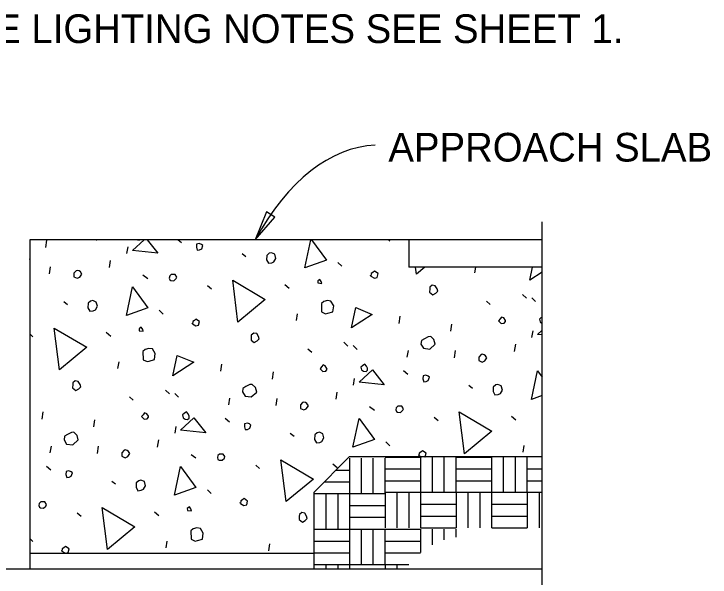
# Model space of a CAD drawing. Extents: x -1660015.2 to -1659984.9, y 2580594.2 to 2580616.7.
# Drawn here: x -1659989.055 to -1659985.382, y 2580602.277 to 2580605.246 of the extents above; entities that cross this region are included whole.
import ezdxf

# ---------------------------------------------------------------- set-up
doc = ezdxf.new("R2010")
doc.units = 0
for name, color, linetype in [('Default', 7, 'Continuous'), ('Miscellaneous', 7, 'Continuous'), ('Miscellaneous3', 7, 'Continuous'), ('PlotBorder_dp', 7, 'Continuous'), ('SheetLines_dp', 7, 'Continuous')]:
    doc.layers.add(name, color=color, linetype=linetype)

msp = doc.modelspace()

# ---------------------------------------------------------------- linework, layer by layer
at = {"layer": 'Default'}
msp.add_line((-1659986.2685, 2580602.3187), (-1659989.3273, 2580602.3187), dxfattribs=at)
at = {"layer": 'Miscellaneous'}
for p, q in [((-1659988.8871, 2580604.0154), (-1659988.8816, 2580604.0531)), ((-1659988.1893, 2580604.056), (-1659988.1719, 2580604.0414)), ((-1659987.0793, 2580604.056), (-1659987.0714, 2580604.049)), ((-1659986.2685, 2580604.056), (-1659986.972, 2580604.056)), ((-1659988.459, 2580603.9826), (-1659988.4529, 2580604.0178)), ((-1659987.8507, 2580603.9825), (-1659987.8311, 2580603.967)), ((-1659988.5505, 2580603.9089), (-1659988.5451, 2580603.9465)), ((-1659987.3466, 2580603.9364), (-1659987.3257, 2580603.9161)), ((-1659988.8677, 2580603.8756), (-1659988.8623, 2580603.9133)), ((-1659986.6228, 2580603.8819), (-1659986.618, 2580603.9102)), ((-1659988.3746, 2580603.8706), (-1659988.3488, 2580603.8516)), ((-1659988.0335, 2580603.8145), (-1659988.0132, 2580603.7966)), ((-1659987.626, 2580603.8201), (-1659987.6027, 2580603.8005)), ((-1659986.3723, 2580603.7678), (-1659986.3513, 2580603.7476)), ((-1659986.3235, 2580603.7498), (-1659986.3025, 2580603.7296)), ((-1659988.7925, 2580603.7301), (-1659988.7728, 2580603.7147)), ((-1659986.5621, 2580603.7325), (-1659986.5418, 2580603.7146)), ((-1659988.2884, 2580603.684), (-1659988.2674, 2580603.6638)), ((-1659987.5646, 2580603.6295), (-1659987.5585, 2580603.6648)), ((-1659987.0222, 2580603.6144), (-1659987.0168, 2580603.6521)), ((-1659986.7499, 2580603.5735), (-1659986.7444, 2580603.6112)), ((-1659988.5678, 2580603.5678), (-1659988.5444, 2580603.5481)), ((-1659986.3218, 2580603.5407), (-1659986.3157, 2580603.5759)), ((-1659988.972, 2580603.5592), (-1659988.9549, 2580603.5443)), ((-1659987.3141, 2580603.5155), (-1659987.2931, 2580603.4952)), ((-1659987.2653, 2580603.4975), (-1659987.2443, 2580603.4772)), ((-1659986.4133, 2580603.4669), (-1659986.4079, 2580603.5046)), ((-1659987.5039, 2580603.4801), (-1659987.4836, 2580603.4623)), ((-1659986.9798, 2580603.4368), (-1659986.9737, 2580603.4721)), ((-1659986.7305, 2580603.4337), (-1659986.7251, 2580603.4714)), ((-1659988.5064, 2580603.3772), (-1659988.5003, 2580603.4124)), ((-1659987.964, 2580603.362), (-1659987.9586, 2580603.3997)), ((-1659987.6916, 2580603.3211), (-1659987.6862, 2580603.3588)), ((-1659986.9999, 2580603.3667), (-1659986.9765, 2580603.3471)), ((-1659987.2636, 2580603.2883), (-1659987.2575, 2580603.3236)), ((-1659986.6553, 2580603.2882), (-1659986.6356, 2580603.2728)), ((-1659988.2558, 2580603.2631), (-1659988.2349, 2580603.2429)), ((-1659988.207, 2580603.2451), (-1659988.1861, 2580603.2249)), ((-1659987.3551, 2580603.2146), (-1659987.3497, 2580603.2523)), ((-1659988.4457, 2580603.2278), (-1659988.4254, 2580603.2099)), ((-1659987.9216, 2580603.1845), (-1659987.9155, 2580603.2197)), ((-1659987.6723, 2580603.1814), (-1659987.6669, 2580603.2191)), ((-1659987.1792, 2580603.1763), (-1659987.1534, 2580603.1574)), ((-1659988.9058, 2580603.1097), (-1659988.9003, 2580603.1474)), ((-1659986.4306, 2580603.1258), (-1659986.4073, 2580603.1062)), ((-1659988.6334, 2580603.0688), (-1659988.628, 2580603.1065)), ((-1659987.9416, 2580603.1144), (-1659987.9183, 2580603.0948)), ((-1659986.838, 2580603.1202), (-1659986.8177, 2580603.1024)), ((-1659988.2053, 2580603.036), (-1659988.1993, 2580603.0712)), ((-1659987.5971, 2580603.0359), (-1659987.5774, 2580603.0204)), ((-1659988.2969, 2580602.9623), (-1659988.2914, 2580602.9999)), ((-1659987.093, 2580602.9898), (-1659987.072, 2580602.9695)), ((-1659988.8634, 2580602.9321), (-1659988.8573, 2580602.9674)), ((-1659988.6141, 2580602.929), (-1659988.6087, 2580602.9667)), ((-1659986.3692, 2580602.9352), (-1659986.3631, 2580602.9705)), ((-1659988.121, 2580602.924), (-1659988.0952, 2580602.905)), ((-1659987.2832, 2580602.5297), (-1659987.2832, 2580602.9035)), ((-1659987.2219, 2580602.7172), (-1659987.2219, 2580602.9035)), ((-1659987.1594, 2580602.7172), (-1659987.1594, 2580602.9035)), ((-1659987.0971, 2580602.9101), (-1659986.9083, 2580602.9101)), ((-1659987.0969, 2580602.7172), (-1659987.0969, 2580602.9035)), ((-1659986.9083, 2580602.5364), (-1659986.9083, 2580602.9101)), ((-1659986.8471, 2580602.7239), (-1659986.8471, 2580602.9101)), ((-1659986.7846, 2580602.7239), (-1659986.7846, 2580602.9101)), ((-1659986.7221, 2580602.9101), (-1659986.5333, 2580602.9101)), ((-1659986.7221, 2580602.7239), (-1659986.7221, 2580602.9101)), ((-1659986.5333, 2580602.5364), (-1659986.5333, 2580602.9101)), ((-1659986.4721, 2580602.7239), (-1659986.4721, 2580602.9101)), ((-1659986.4096, 2580602.7239), (-1659986.4096, 2580602.9101)), ((-1659986.3471, 2580602.7239), (-1659986.3471, 2580602.9101)), ((-1659987.7798, 2580602.8679), (-1659987.7595, 2580602.85)), ((-1659987.3724, 2580602.8735), (-1659987.349, 2580602.8539)), ((-1659988.8834, 2580602.862), (-1659988.86, 2580602.8424)), ((-1659987.3564, 2580602.841), (-1659987.2832, 2580602.841)), ((-1659987.0971, 2580602.8476), (-1659986.9083, 2580602.8476)), ((-1659986.7221, 2580602.8476), (-1659986.5333, 2580602.8476)), ((-1659986.3471, 2580602.8477), (-1659986.2685, 2580602.8477)), ((-1659988.5389, 2580602.7835), (-1659988.5192, 2580602.7681)), ((-1659987.4189, 2580602.7785), (-1659987.2832, 2580602.7785)), ((-1659987.0971, 2580602.7851), (-1659986.9083, 2580602.7851)), ((-1659986.7221, 2580602.7851), (-1659986.5333, 2580602.7851)), ((-1659986.3471, 2580602.7852), (-1659986.2685, 2580602.7852)), ((-1659988.0348, 2580602.7374), (-1659988.0138, 2580602.7172)), ((-1659987.0971, 2580602.7239), (-1659986.7221, 2580602.7239)), ((-1659987.0971, 2580602.7239), (-1659987.0971, 2580602.5364)), ((-1659987.0346, 2580602.7239), (-1659987.0346, 2580602.5364)), ((-1659986.9721, 2580602.7239), (-1659986.9721, 2580602.5364)), ((-1659986.7221, 2580602.7239), (-1659986.3471, 2580602.7239)), ((-1659986.7221, 2580602.7239), (-1659986.7221, 2580602.5364)), ((-1659986.6596, 2580602.7239), (-1659986.6596, 2580602.5364)), ((-1659986.5971, 2580602.7239), (-1659986.5971, 2580602.5364)), ((-1659986.3471, 2580602.7239), (-1659986.2685, 2580602.7239)), ((-1659986.3471, 2580602.7239), (-1659986.3471, 2580602.5364)), ((-1659986.2846, 2580602.7239), (-1659986.2846, 2580602.5364)), ((-1659987.4719, 2580602.7172), (-1659987.0969, 2580602.7172)), ((-1659987.4094, 2580602.7172), (-1659987.4094, 2580602.5297)), ((-1659987.3469, 2580602.7172), (-1659987.3469, 2580602.5297)), ((-1659987.2832, 2580602.6547), (-1659987.0969, 2580602.6547)), ((-1659986.9083, 2580602.6614), (-1659986.7221, 2580602.6614)), ((-1659986.5333, 2580602.6614), (-1659986.3471, 2580602.6614)), ((-1659988.7216, 2580602.6155), (-1659988.7013, 2580602.5977)), ((-1659988.3142, 2580602.6211), (-1659988.2908, 2580602.6015)), ((-1659987.2832, 2580602.5922), (-1659987.0969, 2580602.5922)), ((-1659986.9083, 2580602.5989), (-1659986.7221, 2580602.5989)), ((-1659986.5333, 2580602.5989), (-1659986.3471, 2580602.5989)), ((-1659986.9083, 2580602.5364), (-1659986.7221, 2580602.5364)), ((-1659986.5333, 2580602.5364), (-1659986.3471, 2580602.5364)), ((-1659987.4719, 2580602.5297), (-1659987.2832, 2580602.5297)), ((-1659987.2832, 2580602.3187), (-1659987.2832, 2580602.5298)), ((-1659987.2832, 2580602.5297), (-1659987.0969, 2580602.5297)), ((-1659987.2219, 2580602.3435), (-1659987.2219, 2580602.5297)), ((-1659987.1594, 2580602.3435), (-1659987.1594, 2580602.5297)), ((-1659987.0969, 2580602.5297), (-1659986.9082, 2580602.5297)), ((-1659987.0969, 2580602.3435), (-1659987.0969, 2580602.5297)), ((-1659986.9082, 2580602.4069), (-1659986.9082, 2580602.5298)), ((-1659986.8469, 2580602.447), (-1659986.8469, 2580602.5298)), ((-1659986.7844, 2580602.4735), (-1659986.7844, 2580602.5298)), ((-1659986.7219, 2580602.4875), (-1659986.7219, 2580602.5298)), ((-1659988.972, 2580602.4807), (-1659988.9556, 2580602.4648)), ((-1659988.2528, 2580602.4306), (-1659988.2467, 2580602.4658)), ((-1659987.4719, 2580602.4672), (-1659987.2832, 2580602.4672)), ((-1659987.0969, 2580602.4672), (-1659986.9082, 2580602.4672)), ((-1659987.7104, 2580602.4154), (-1659987.7049, 2580602.4531)), ((-1659987.472, 2580602.402), (-1659988.972, 2580602.402)), ((-1659987.4719, 2580602.4047), (-1659987.2832, 2580602.4047)), ((-1659987.0969, 2580602.4048), (-1659986.9108, 2580602.4048)), ((-1659987.4719, 2580602.3435), (-1659987.0969, 2580602.3435)), ((-1659987.4094, 2580602.3435), (-1659987.4094, 2580602.3187)), ((-1659987.3469, 2580602.3435), (-1659987.3469, 2580602.3187)), ((-1659987.0969, 2580602.3435), (-1659986.9711, 2580602.3435)), ((-1659987.0969, 2580602.3435), (-1659987.0969, 2580602.3187)), ((-1659987.0344, 2580602.3435), (-1659987.0344, 2580602.3187)), ((-1659986.9719, 2580602.3435), (-1659986.9719, 2580602.3425))]:
    msp.add_line(p, q, dxfattribs=at)
for points in [[(-1659988.6212, 2580604.056), (-1659988.6209, 2580604.0556), (-1659988.6176, 2580604.056)], [(-1659988.4295, 2580603.9982), (-1659988.3674, 2580604.056)], [(-1659988.3529, 2580604.056), (-1659988.2965, 2580603.9847), (-1659988.4295, 2580603.9982)], [(-1659988.4041, 2580604.056), (-1659988.3929, 2580604.0546), (-1659988.3914, 2580604.056)], [(-1659987.5202, 2580603.908), (-1659987.4888, 2580604.056)], [(-1659987.486, 2580604.056), (-1659987.4069, 2580603.9487), (-1659987.5202, 2580603.908)], [(-1659988.0926, 2580604.016), (-1659988.0888, 2580604.0015), (-1659988.076, 2580604.0023), (-1659988.0646, 2580604.008), (-1659988.0588, 2580604.0251), (-1659988.0656, 2580604.031), (-1659988.0772, 2580604.0357), (-1659988.0917, 2580604.0318), (-1659988.0926, 2580604.016)], [(-1659987.7214, 2580603.9731), (-1659987.7228, 2580603.9495), (-1659987.7128, 2580603.9314), (-1659987.6953, 2580603.9336), (-1659987.6838, 2580603.9392), (-1659987.6732, 2580603.9576), (-1659987.6791, 2580603.9793), (-1659987.6968, 2580603.9875), (-1659987.7089, 2580603.9843), (-1659987.7214, 2580603.9731)], [(-1659988.972, 2580603.9446), (-1659988.9696, 2580603.9467), (-1659988.972, 2580603.9556)], [(-1659988.7392, 2580603.879), (-1659988.7395, 2580603.8608), (-1659988.7218, 2580603.8526), (-1659988.708, 2580603.8589), (-1659988.6967, 2580603.8749), (-1659988.7048, 2580603.8856), (-1659988.7115, 2580603.8916), (-1659988.7225, 2580603.8938), (-1659988.7273, 2580603.8925), (-1659988.7392, 2580603.879)], [(-1659986.9314, 2580603.8742), (-1659986.9359, 2580603.9102)], [(-1659986.8878, 2580603.9102), (-1659986.9314, 2580603.8742)], [(-1659986.3329, 2580603.8431), (-1659986.3185, 2580603.9102)], [(-1659988.2329, 2580603.8439), (-1659988.2267, 2580603.8403), (-1659988.211, 2580603.8394), (-1659988.1984, 2580603.8505), (-1659988.1955, 2580603.859), (-1659988.2042, 2580603.8722), (-1659988.2249, 2580603.8719), (-1659988.2332, 2580603.8645), (-1659988.2355, 2580603.8535), (-1659988.2329, 2580603.8439)], [(-1659987.172, 2580603.8641), (-1659987.1536, 2580603.8535), (-1659987.1391, 2580603.8574), (-1659987.134, 2580603.8769), (-1659987.153, 2580603.8899), (-1659987.1614, 2580603.8825), (-1659987.1704, 2580603.8775), (-1659987.172, 2580603.8641), (-1659987.1733, 2580603.869)], [(-1659986.2685, 2580603.8845), (-1659986.3329, 2580603.8431)], [(-1659987.8732, 2580603.6219), (-1659987.9011, 2580603.8422), (-1659987.729, 2580603.7408), (-1659987.8732, 2580603.6219)], [(-1659987.4521, 2580603.8279), (-1659987.4309, 2580603.8258), (-1659987.4335, 2580603.8355), (-1659987.4415, 2580603.8463), (-1659987.4523, 2580603.8382), (-1659987.4521, 2580603.8279)], [(-1659988.462, 2580603.6556), (-1659988.4299, 2580603.8066), (-1659988.3486, 2580603.6964), (-1659988.462, 2580603.6556)], [(-1659986.8616, 2580603.7972), (-1659986.8619, 2580603.779), (-1659986.8453, 2580603.7653), (-1659986.8297, 2580603.7747), (-1659986.8195, 2580603.7852), (-1659986.8228, 2580603.7972), (-1659986.8321, 2580603.8128), (-1659986.8485, 2580603.8162), (-1659986.8611, 2580603.8051), (-1659986.8616, 2580603.7972)], [(-1659988.6632, 2580603.7208), (-1659988.6646, 2580603.6971), (-1659988.6546, 2580603.6791), (-1659988.637, 2580603.6812), (-1659988.6256, 2580603.6869), (-1659988.615, 2580603.7052), (-1659988.6208, 2580603.727), (-1659988.6386, 2580603.7352), (-1659988.6506, 2580603.7319), (-1659988.6632, 2580603.7208)], [(-1659987.4333, 2580603.719), (-1659987.432, 2580603.6754), (-1659987.4112, 2580603.6654), (-1659987.3991, 2580603.6687), (-1659987.3726, 2580603.6758), (-1659987.3682, 2580603.708), (-1659987.3826, 2580603.7326), (-1659987.4015, 2580603.7353), (-1659987.4208, 2580603.7302), (-1659987.4333, 2580603.719)], [(-1659987.2747, 2580603.5907), (-1659987.2516, 2580603.6978), (-1659987.1643, 2580603.6617), (-1659987.2747, 2580603.5907)], [(-1659988.1137, 2580603.6118), (-1659988.0954, 2580603.6012), (-1659988.0809, 2580603.6051), (-1659988.0758, 2580603.6245), (-1659988.0948, 2580603.6376), (-1659988.1031, 2580603.6302), (-1659988.1121, 2580603.6251), (-1659988.1137, 2580603.6118), (-1659988.115, 2580603.6166)], [(-1659986.4979, 2580603.628), (-1659986.4837, 2580603.6137), (-1659986.4686, 2580603.6152), (-1659986.4609, 2580603.625), (-1659986.4621, 2580603.6299), (-1659986.4709, 2580603.6431), (-1659986.4825, 2580603.6477), (-1659986.4902, 2580603.6379), (-1659986.4979, 2580603.628)], [(-1659986.2685, 2580603.6479), (-1659986.2744, 2580603.6439), (-1659986.2828, 2580603.6365), (-1659986.2789, 2580603.622)], [(-1659986.2789, 2580603.622), (-1659986.269, 2580603.6143), (-1659986.2685, 2580603.6142)], [(-1659988.8149, 2580603.3695), (-1659988.8429, 2580603.5898), (-1659988.6708, 2580603.4884), (-1659988.8149, 2580603.3695)], [(-1659988.3939, 2580603.5755), (-1659988.3726, 2580603.5735), (-1659988.3752, 2580603.5831), (-1659988.3833, 2580603.5939), (-1659988.3941, 2580603.5858), (-1659988.3939, 2580603.5755)], [(-1659987.8033, 2580603.5448), (-1659987.8036, 2580603.5266), (-1659987.787, 2580603.513), (-1659987.7714, 2580603.5223), (-1659987.7613, 2580603.5328), (-1659987.7645, 2580603.5449), (-1659987.7739, 2580603.5605), (-1659987.7903, 2580603.5639), (-1659987.8029, 2580603.5527), (-1659987.8033, 2580603.5448)], [(-1659986.2923, 2580603.5563), (-1659986.2685, 2580603.5785)], [(-1659986.9076, 2580603.5053), (-1659986.8939, 2580603.4831), (-1659986.8617, 2580603.4788), (-1659986.8324, 2580603.5048), (-1659986.8389, 2580603.5289), (-1659986.8561, 2580603.545), (-1659986.8688, 2580603.5442), (-1659986.8893, 2580603.5335), (-1659986.9049, 2580603.5242), (-1659986.9076, 2580603.5053)], [(-1659986.2685, 2580603.5539), (-1659986.2923, 2580603.5563)], [(-1659988.3751, 2580603.4667), (-1659988.3738, 2580603.4231), (-1659988.353, 2580603.4131), (-1659988.3409, 2580603.4163), (-1659988.3143, 2580603.4234), (-1659988.31, 2580603.4557), (-1659988.3244, 2580603.4803), (-1659988.3432, 2580603.483), (-1659988.3626, 2580603.4778), (-1659988.3751, 2580603.4667)], [(-1659988.2165, 2580603.3384), (-1659988.1934, 2580603.4455), (-1659988.1061, 2580603.4094), (-1659988.2165, 2580603.3384)], [(-1659986.602, 2580603.4371), (-1659986.6023, 2580603.4189), (-1659986.5846, 2580603.4107), (-1659986.5708, 2580603.417), (-1659986.5595, 2580603.433), (-1659986.5676, 2580603.4437), (-1659986.5743, 2580603.4497), (-1659986.5853, 2580603.4519), (-1659986.5901, 2580603.4506), (-1659986.602, 2580603.4371)], [(-1659987.4397, 2580603.3757), (-1659987.4255, 2580603.3614), (-1659987.4103, 2580603.3629), (-1659987.4026, 2580603.3727), (-1659987.4039, 2580603.3775), (-1659987.4126, 2580603.3907), (-1659987.4242, 2580603.3954), (-1659987.432, 2580603.3855), (-1659987.4397, 2580603.3757)], [(-1659987.2207, 2580603.3697), (-1659987.2108, 2580603.362), (-1659987.1975, 2580603.3604), (-1659987.1891, 2580603.3678), (-1659987.1893, 2580603.3781), (-1659987.1949, 2580603.3895), (-1659987.203, 2580603.4003), (-1659987.2162, 2580603.3916), (-1659987.2245, 2580603.3842), (-1659987.2207, 2580603.3697)], [(-1659987.2341, 2580603.304), (-1659987.1636, 2580603.3694), (-1659987.1011, 2580603.2904), (-1659987.2341, 2580603.304)], [(-1659986.3248, 2580603.2137), (-1659986.2927, 2580603.3647), (-1659986.2685, 2580603.3318)], [(-1659988.7451, 2580603.2925), (-1659988.7454, 2580603.2743), (-1659988.7288, 2580603.2606), (-1659988.7132, 2580603.27), (-1659988.7031, 2580603.2805), (-1659988.7063, 2580603.2925), (-1659988.7157, 2580603.3081), (-1659988.7321, 2580603.3115), (-1659988.7446, 2580603.3004), (-1659988.7451, 2580603.2925)], [(-1659986.8972, 2580603.3218), (-1659986.8933, 2580603.3073), (-1659986.8806, 2580603.3081), (-1659986.8692, 2580603.3137), (-1659986.8634, 2580603.3308), (-1659986.8702, 2580603.3368), (-1659986.8818, 2580603.3414), (-1659986.8963, 2580603.3375), (-1659986.8972, 2580603.3218)], [(-1659987.8494, 2580603.253), (-1659987.8357, 2580603.2308), (-1659987.8034, 2580603.2265), (-1659987.7742, 2580603.2524), (-1659987.7806, 2580603.2766), (-1659987.7979, 2580603.2927), (-1659987.8106, 2580603.2918), (-1659987.831, 2580603.2812), (-1659987.8467, 2580603.2718), (-1659987.8494, 2580603.253)], [(-1659986.526, 2580603.2789), (-1659986.5274, 2580603.2552), (-1659986.5174, 2580603.2372), (-1659986.4998, 2580603.2393), (-1659986.4884, 2580603.2449), (-1659986.4778, 2580603.2633), (-1659986.4836, 2580603.2851), (-1659986.5014, 2580603.2932), (-1659986.5134, 2580603.29), (-1659986.526, 2580603.2789)], [(-1659986.2685, 2580603.234), (-1659986.3248, 2580603.2137)], [(-1659987.5438, 2580603.1847), (-1659987.5441, 2580603.1665), (-1659987.5264, 2580603.1584), (-1659987.5125, 2580603.1647), (-1659987.5013, 2580603.1806), (-1659987.5093, 2580603.1914), (-1659987.5161, 2580603.1973), (-1659987.5271, 2580603.1996), (-1659987.5319, 2580603.1983), (-1659987.5438, 2580603.1847)], [(-1659987.0374, 2580603.1496), (-1659987.0313, 2580603.1461), (-1659987.0155, 2580603.1451), (-1659987.003, 2580603.1562), (-1659987.0001, 2580603.1648), (-1659987.0088, 2580603.178), (-1659987.0294, 2580603.1776), (-1659987.0378, 2580603.1702), (-1659987.04, 2580603.1593), (-1659987.0374, 2580603.1496)], [(-1659988.3815, 2580603.1234), (-1659988.3673, 2580603.109), (-1659988.3521, 2580603.1105), (-1659988.3444, 2580603.1203), (-1659988.3457, 2580603.1252), (-1659988.3544, 2580603.1384), (-1659988.366, 2580603.143), (-1659988.3737, 2580603.1332), (-1659988.3815, 2580603.1234)], [(-1659988.1624, 2580603.1173), (-1659988.1526, 2580603.1096), (-1659988.1392, 2580603.108), (-1659988.1309, 2580603.1154), (-1659988.131, 2580603.1257), (-1659988.1367, 2580603.1372), (-1659988.1448, 2580603.148), (-1659988.1579, 2580603.1392), (-1659988.1663, 2580603.1318), (-1659988.1624, 2580603.1173)], [(-1659986.6777, 2580602.9276), (-1659986.7057, 2580603.1479), (-1659986.5336, 2580603.0465), (-1659986.6777, 2580602.9276)], [(-1659988.1759, 2580603.0516), (-1659988.1054, 2580603.1171), (-1659988.0428, 2580603.0381), (-1659988.1759, 2580603.0516)], [(-1659987.839, 2580603.0694), (-1659987.8351, 2580603.0549), (-1659987.8224, 2580603.0557), (-1659987.811, 2580603.0614), (-1659987.8052, 2580603.0785), (-1659987.812, 2580603.0844), (-1659987.8236, 2580603.0891), (-1659987.8381, 2580603.0852), (-1659987.839, 2580603.0694)], [(-1659987.2665, 2580602.9614), (-1659987.2345, 2580603.1123), (-1659987.1532, 2580603.0021), (-1659987.2665, 2580602.9614)], [(-1659988.7911, 2580603.0006), (-1659988.7774, 2580602.9784), (-1659988.7452, 2580602.9741), (-1659988.7159, 2580603.0001), (-1659988.7224, 2580603.0242), (-1659988.7397, 2580603.0403), (-1659988.7524, 2580603.0395), (-1659988.7728, 2580603.0288), (-1659988.7884, 2580603.0195), (-1659988.7911, 2580603.0006)], [(-1659987.4678, 2580603.0265), (-1659987.4692, 2580603.0029), (-1659987.4592, 2580602.9848), (-1659987.4416, 2580602.9869), (-1659987.4302, 2580602.9926), (-1659987.4196, 2580603.011), (-1659987.4254, 2580603.0327), (-1659987.4431, 2580603.0409), (-1659987.4552, 2580603.0377), (-1659987.4678, 2580603.0265)], [(-1659988.4856, 2580602.9324), (-1659988.4859, 2580602.9142), (-1659988.4682, 2580602.906), (-1659988.4543, 2580602.9123), (-1659988.4431, 2580602.9283), (-1659988.4511, 2580602.939), (-1659988.4579, 2580602.945), (-1659988.4688, 2580602.9472), (-1659988.4737, 2580602.9459), (-1659988.4856, 2580602.9324)], [(-1659986.8878, 2580602.9102), (-1659986.8855, 2580602.9108), (-1659986.8803, 2580602.9303), (-1659986.8994, 2580602.9433), (-1659986.9077, 2580602.9359), (-1659986.9167, 2580602.9309), (-1659986.9183, 2580602.9175), (-1659986.9196, 2580602.9224)], [(-1659987.9792, 2580602.8972), (-1659987.9731, 2580602.8937), (-1659987.9573, 2580602.8928), (-1659987.9448, 2580602.9039), (-1659987.9419, 2580602.9124), (-1659987.9506, 2580602.9256), (-1659987.9712, 2580602.9253), (-1659987.9796, 2580602.9179), (-1659987.9818, 2580602.9069), (-1659987.9792, 2580602.8972)], [(-1659986.9183, 2580602.9175), (-1659986.9056, 2580602.9102)], [(-1659987.6195, 2580602.6753), (-1659987.6475, 2580602.8956), (-1659987.4754, 2580602.7941), (-1659987.6195, 2580602.6753)], [(-1659988.7808, 2580602.8171), (-1659988.7769, 2580602.8026), (-1659988.7642, 2580602.8034), (-1659988.7528, 2580602.809), (-1659988.747, 2580602.8261), (-1659988.7537, 2580602.8321), (-1659988.7653, 2580602.8367), (-1659988.7798, 2580602.8328), (-1659988.7808, 2580602.8171)], [(-1659988.2083, 2580602.709), (-1659988.1763, 2580602.86), (-1659988.095, 2580602.7498), (-1659988.2083, 2580602.709)], [(-1659988.4095, 2580602.7742), (-1659988.411, 2580602.7505), (-1659988.401, 2580602.7325), (-1659988.3834, 2580602.7346), (-1659988.372, 2580602.7402), (-1659988.3614, 2580602.7586), (-1659988.3672, 2580602.7804), (-1659988.3849, 2580602.7885), (-1659988.397, 2580602.7853), (-1659988.4095, 2580602.7742)], [(-1659987.8601, 2580602.6652), (-1659987.8417, 2580602.6546), (-1659987.8272, 2580602.6584), (-1659987.8221, 2580602.6779), (-1659987.8411, 2580602.691), (-1659987.8495, 2580602.6835), (-1659987.8585, 2580602.6785), (-1659987.8601, 2580602.6652), (-1659987.8614, 2580602.67)], [(-1659988.921, 2580602.6449), (-1659988.9149, 2580602.6414), (-1659988.8991, 2580602.6404), (-1659988.8865, 2580602.6515), (-1659988.8837, 2580602.6601), (-1659988.8924, 2580602.6733), (-1659988.913, 2580602.6729), (-1659988.9214, 2580602.6655), (-1659988.9236, 2580602.6546), (-1659988.921, 2580602.6449)], [(-1659988.1403, 2580602.6289), (-1659988.119, 2580602.6269), (-1659988.1216, 2580602.6365), (-1659988.1297, 2580602.6473), (-1659988.1404, 2580602.6392), (-1659988.1403, 2580602.6289)], [(-1659988.5613, 2580602.4229), (-1659988.5893, 2580602.6432), (-1659988.4171, 2580602.5418), (-1659988.5613, 2580602.4229)], [(-1659987.5497, 2580602.5982), (-1659987.55, 2580602.58), (-1659987.5334, 2580602.5664), (-1659987.5178, 2580602.5757), (-1659987.5077, 2580602.5862), (-1659987.5109, 2580602.5983), (-1659987.5202, 2580602.6139), (-1659987.5367, 2580602.6172), (-1659987.5492, 2580602.6061), (-1659987.5497, 2580602.5982)], [(-1659988.1215, 2580602.5201), (-1659988.1201, 2580602.4764), (-1659988.0993, 2580602.4665), (-1659988.0873, 2580602.4697), (-1659988.0607, 2580602.4768), (-1659988.0564, 2580602.5091), (-1659988.0707, 2580602.5337), (-1659988.0896, 2580602.5364), (-1659988.1089, 2580602.5312), (-1659988.1215, 2580602.5201)], [(-1659988.8019, 2580602.4128), (-1659988.7835, 2580602.4022), (-1659988.769, 2580602.4061), (-1659988.7639, 2580602.4256), (-1659988.7829, 2580602.4386), (-1659988.7913, 2580602.4312), (-1659988.8003, 2580602.4262), (-1659988.8019, 2580602.4128), (-1659988.8032, 2580602.4177)]]:
    msp.add_lwpolyline(points, dxfattribs=at)
at = {"layer": 'Miscellaneous3'}
for p, q in [((-1659986.972, 2580604.056), (-1659988.972, 2580604.056)), ((-1659988.972, 2580604.056), (-1659988.972, 2580602.681)), ((-1659986.972, 2580604.056), (-1659986.972, 2580603.9102)), ((-1659986.2685, 2580603.9102), (-1659986.972, 2580603.9102)), ((-1659987.472, 2580602.7255), (-1659987.2873, 2580602.9102)), ((-1659986.2685, 2580602.9102), (-1659987.2873, 2580602.9102)), ((-1659987.472, 2580602.3187), (-1659987.472, 2580602.7255)), ((-1659988.972, 2580602.681), (-1659988.972, 2580602.3187))]:
    msp.add_line(p, q, dxfattribs=at)
at = {"layer": 'SheetLines_dp'}
msp.add_lwpolyline([(-1659987.7832, 2580604.0558), (-1659987.6785, 2580604.1748), (-1659987.7235, 2580604.2026)], close=True, dxfattribs=at)
msp.add_lwpolyline([(-1659986.2685, 2580601.863), (-1659986.2685, 2580604.1496)], dxfattribs=at)
msp.add_ellipse((-1659987.0381, 2580602.1871), major_axis=(0.1111, -2.3674), ratio=0.464296, start_param=3.141604, end_param=3.781059, dxfattribs=at)

# ---------------------------------------------------------------- texts
at = {"layer": 'PlotBorder_dp'}
msp.add_text('APPROACH SLAB', height=0.1512, dxfattribs=at).set_placement((-1659987.0795, 2580604.468))
at = {"layer": 'SheetLines_dp'}
msp.add_text('1.  FOR BOX GIRDER MAINTENANCE LIGHTING NOTES SEE SHEET 1.', height=0.1512, dxfattribs=at).set_placement((-1659992.5804, 2580605.0929))

doc.saveas('drawing.dxf')
